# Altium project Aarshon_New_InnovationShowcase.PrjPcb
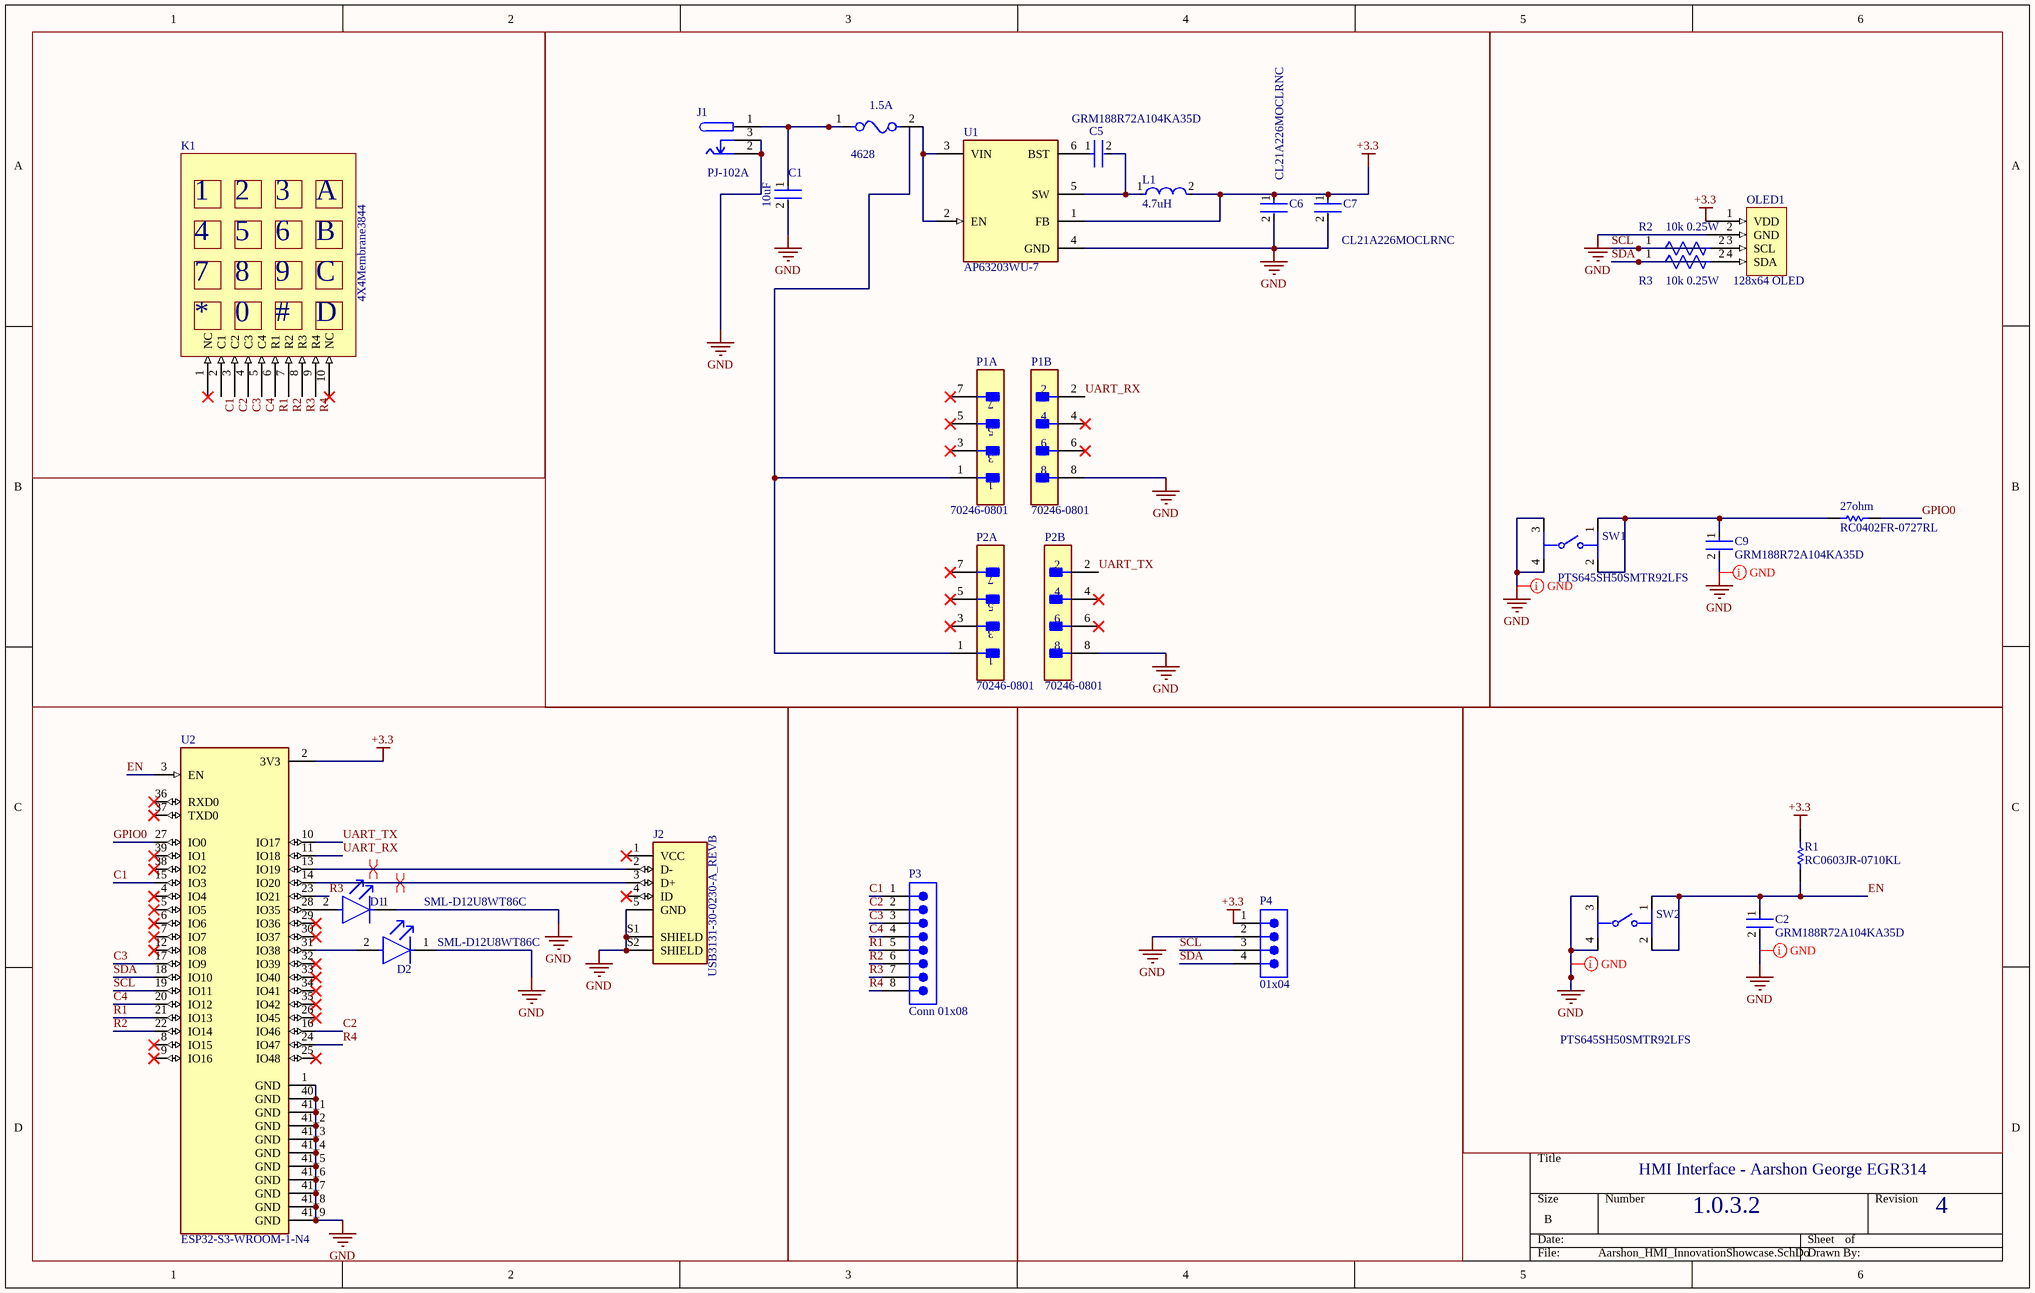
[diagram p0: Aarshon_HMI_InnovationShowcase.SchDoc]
1 sheet, 26 parts. Net scope: global (net labels, ports and power ports of the same name join across sheets).
Board file: HMI_PrintReview.PcbDoc

## Sheet Aarshon_HMI_InnovationShowcase.SchDoc
size B; SheetNumber: 1; SheetTotal: 1

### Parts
1.5A  4628  [4628-Footprint-1]
27ohm  RC0402FR-0727RL  [RESC1005X40X25LL05T10]
C1  10uF  [FP-C1210C106M6PACTU-MFG]
C2  GRM188R72A104KA35D  [FP-GRM188-0_1-e0_2_0_5-MFG]
C5  GRM188R72A104KA35D  [FP-GRM188-0_1-e0_2_0_5-MFG]
C6  CL21A226MOCLRNC  [FP-CL21-IPC_C]
C7  CL21A226MOCLRNC  [FP-CL21-IPC_C]
C9  GRM188R72A104KA35D  [FP-GRM188-0_1-e0_2_0_5-MFG]
D1  SML-D12U8WT86C  [FP-SML-D12-MFG]
D2  SML-D12U8WT86C  [FP-SML-D12-MFG]
J1  PJ-102A  [FP-PJ-102A-MFG]
J2  USB3131-30-0230-A_REVB  [GCT_USB3131-30-0230-A_REVB]
K1  4X4Membrane3844
L1  4.7uH  [FP-IHLP-2525EZ-FP_2_413x3-MFG]
OLED1  128x64 OLED
P1  70246-0801  [FP-0702460801-MFG]  (parts A,B of 2)
P2  70246-0801  [FP-0702460801-MFG]  (parts A,B of 2)
P3  Conn 01x08  [61300811121]
P4  01x04  [61300411121]
R1  RC0603JR-0710KL  [RESC1608X55X25ML10T15]
R2  10k 0.25W  [FP-CR1206-IPC_C]
R3  10k 0.25W  [FP-CR1206-IPC_C]
SW1  PTS645SH50SMTR92LFS  [FP-PTS645SH50SMTR92LFS-MFG]
SW2  PTS645SH50SMTR92LFS  [FP-PTS645SH50SMTR92LFS-MFG]
U1  AP63203WU-7  [FP-TSOT26-MFG]
U2  ESP32-S3-WROOM-1-N4  [XCVR_ESP32-S3-WROOM-1-N4]

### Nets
+3.3: C6.1 C7.1 L1.2 OLED1.1(VDD) P4.1 R1.2 U1.1(FB) U2.2(3V3)
GND: C1.2 C2.2 C6.2 C7.2 C9.2 D1.1(C) D2.1(C) J1.2 J1.3 J2.5(GND) J2.S1(SHIELD) J2.S2(SHIELD) OLED1.2(GND) P1.8 P2.8 P4.2 SW1.3 SW1.4 SW2.3 SW2.4 U1.4(GND) U2.1(GND) U2.40(GND) U2.41_1(GND) U2.41_2(GND) U2.41_3(GND) U2.41_4(GND) U2.41_5(GND) U2.41_6(GND) U2.41_7(GND) U2.41_8(GND) U2.41_9(GND)
C1: K1.2(C1) P3.1 U2.15(IO3)
C2: K1.3(C2) P3.2 U2.16(IO46)
C3: K1.4(C3) P3.3 U2.17(IO9)
C4: K1.5(C4) P3.4 U2.20(IO12)
EN: C2.1 R1.1 SW2.1 SW2.2 U2.3(EN)
GPIO0: 27ohm.2 U2.27(IO0)
R1: K1.6(R1) P3.5 U2.21(IO13)
R2: K1.7(R2) P3.6 U2.22(IO14)
R3: K1.8(R3) P3.7 U2.23(IO21)
R4: K1.9(R4) P3.8 U2.24(IO47)
SCL: OLED1.3(SCL) P4.3 R2.1 U2.19(IO11)
SDA: OLED1.4(SDA) P4.4 R3.1 U2.18(IO10)
UART_RX: P1.2 U2.11(IO18)
UART_TX: P2.2 U2.10(IO17)
Net1.5A_1: 1.5A.1 C1.1 J1.1
Net1.5A_2: 1.5A.2 U1.2(EN) U1.3(VIN)
Net27ohm_1: 27ohm.1 C9.1 SW1.1 SW1.2
NetC5_1: C5.1 U1.6(BST)
NetC5_2: C5.2 L1.1 U1.5(SW)
NetD1_2: D1.2(A) U2.28(IO35)
NetD2_2: D2.2(A) U2.31(IO38)
NetJ2_2: J2.2(D-) U2.13(IO19)
NetJ2_3: J2.3(D+) U2.14(IO20)
NetP1_1: P1.1 P2.1

Not connected (* = marked no-connect by the designer): J2 1(VCC)* 4(ID)*; K1 1(NC)* 10(NC)*; P1 3* 4* 5* 6* 7*; P2 3* 4* 5* 6* 7*; R2 2; R3 2; U2 4(IO4)* 5(IO5)* 6(IO6)* 7(IO7)* 8(IO15)* 9(IO16)* 12(IO8)* 25(IO48)* 26(IO45)* 29(IO36)* 30(IO37)* 32(IO39)* 33(IO40)* 34(IO41)* 35(IO42)* 36(RXD0)* 37(TXD0)* 38(IO2)* 39(IO1)*

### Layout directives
net class GND: GND
differential pair: NetJ2_2, NetJ2_3

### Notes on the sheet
- HMI Interface - Aarshon George EGR314
- 1.0.3.2
- 4

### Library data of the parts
1.5A = CMP-00029-1: Fuses/Accessories
27ohm = CMP-2002-07055-1: Manufacturer: Yageo / Phycomp
C1 = CMP-1038-02235-2: CAP CER 10UF 35V X5R 1210; Dissipation Factor: 2.5%; Tolerance: 20%; Dielectric Material: Ceramic
C2 C5 C9 = CMP-1035-02595-8: Chip Multilayer Ceramic Capacitors for General Purpose, 0603, 0.10uF, X7R, 15%, 10%, 100V; Capacitance: 100nF
C6 C7 = CMP-13271-002990-1: CL21 Series 0805 22uF 16V ±20% Tolerance X5R Multilayer Ceramic Chip Capacitor
D1 D2 = CMP-08952-000014-1: LED RED 1608 SMD; Manufacturer: Rohm; Reverse Voltage: 5V; Wavelength: 620nm; Luminous Intensity: 63mcd; Automotive Grade: Grade 3; Forward Voltage: 2.2V; Led Orientation: Top View; Forward Current: 20mA; Power Dissipation: 54mW
J1 = CMP-00031-1: 2.0 x 6.5 mm, 2.5 A, Horizontal, Through Hole, Tapered Pins, Dc Power Jack Connector
J2 = CMP-008-000000-2: USB - micro B USB 2.0 Receptacle Connector 5 Position Through Hole
K1 = CMP-00001-1: Adapter; TNC Male to BNC Female; Brass; Brass (Male), Beryllium Copper (Female)
L1 = CMP-00011-1: General Purpose Inductor, 4.7uH, 20%, 1 Element, Composite-Core, SMD, 2525; Test Frequency: 100kHz; Channels: 1; Package Width: 6.47mm; Max Current Rating: 6.5A; Inductor Application: HIGH CURRENT INDUCTOR; Shielding: Shielded; DC Resistance (DCR): 30.3mR; Core Material: Ferrite; Shape/Size Description: RECTANGULAR PACKAGE; Package Length: 6.86mm; Package Height: 5mm; Case/Size Code: 2726
OLED1 = CMP-00043-1: 4 Pin OLED, 0.96 size. SDA, SCL, VDD and GND
P1 P2 = CMP-00034-1: Board Connector, 8 Contact(s), 2 Row(s), Male, Straight, 0.1 inch Pitch, Solder Terminal, Guide Slot, Black Insulator, Receptacle; Manufacturer Series: 70246; Filter Feature: No; Number Of PCB Rows: 2; Body Breadth: 0.35inch; PCB Contact Pattern: RECTANGULAR; Rated Current (Signal): 2.5A; Body Depth: 0.365inch; Dielectric Withstanding Voltage (AC): 900V; Reference Standard: UL; Contact Style: SQ PIN-SKT; Insulation Resistance: 12GR; Polarization Key: POLARIZED HOUSING; Option: General Purpose; Mounting Option 2: LOCKING; Reliability: COMMERCIAL; Plating Thickness: 15uin; Number of Contacts: 8; Additional Feature: SHROUDED; PCB Contact Row Spacing: 2.54mm; Number Of Connectors: 1; Body Length: 0.7inch
P3 = CMP-00017-1: Board Connector, 8 Contact(s), 1 Row(s), Male, Straight, 0.1 inch Pitch, Solder Terminal, Locking, Black Insulator, Plug; Manufacturer Series: 613; Insulation Resistance: 1GR; Number of Contacts: 8; Dielectric Withstanding Voltage (AC): 500V; Contact Resistance: 20mR; Rated Current (Signal): 3A; Reference Standard: UL; PCB Contact Pattern: RECTANGULAR; Reliability: COMMERCIAL; Number Of Connectors: 1; Body Length: 0.8inch; Contact Style: SQ PIN-SKT
P4 = CMP-00044-1: Board Connector, 4 Contact(s), 1 Row(s), Male, Straight, 0.1 inch Pitch, Solder Terminal, Locking, Black Insulator, Plug; Number of Rows Loaded: 1; Contact Resistance: 20mR; Body Length: 0.4inch; Reliability: COMMERCIAL; Dielectric Withstanding Voltage (AC): 500V; Insulation Resistance: 1GR; Contact Style: SQ PIN-SKT; Contact Pattern: RECTANGULAR; Number of Contacts: 4; Rated Current (Signal): 3A; Reference Standard: UL
R1 = CMP-2000-05022-1: Resistor, 10 KOhm, +/- 5%, 100 mW, -55 to 155 degC, 0603 (1608 Metric), RoHS, Tape and Reel; Manufacturer: Yageo; Resistance: 10kOhms; Voltage Rating: 50V; Temperature Coefficient: 100PPM/C; Power Rating: 100mW
R2 R3 = CMP-00022-2: Fixed Resistor, Metal Glaze/thick Film, 0.25W, 10000ohm, 200V, 5% +/-Tol, 200ppm/Cel, Surface Mount, 1206; Package Width: 1.6mm; Power: 250mW; Value: 10kR; Rated Temperature: 70°C; Package Length: 3.2mm; Package Height: 0.6mm; Temperature Coefficient (ppm/Cel): 200
SW1 SW2 = CMP-10040-000028-1: SWITCH TACTILE SPST-NO 0.05A 12V; Operating Force: 200gf; Current Rating: 50mA; Illumination Type: Non-Illuminated; Actuator Material: Nylon; Throw Configuration: SPST; Switch Function: Off-Mom; Mechanical Life: 100000Cycles; Actuator Type: Standard
U1 = CMP-12757-000006-1: IC REG BUCK 3.3V 2A TSOT26; Manufacturer: Diodes Inc.; Output Type: Fixed; Min Supply Voltage: 3.8V; Number Of Outputs: 1; Max Junction Temp: +160°C; Nominal Supply Current: 22uA; Standoff Height: 0.01mm; Switching Frequency: 1.1MHz; Max Supply Voltage: 32V
U2 = CMP-002-000002-1: MF: {'manufacturer': u'Espressif Systems'}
